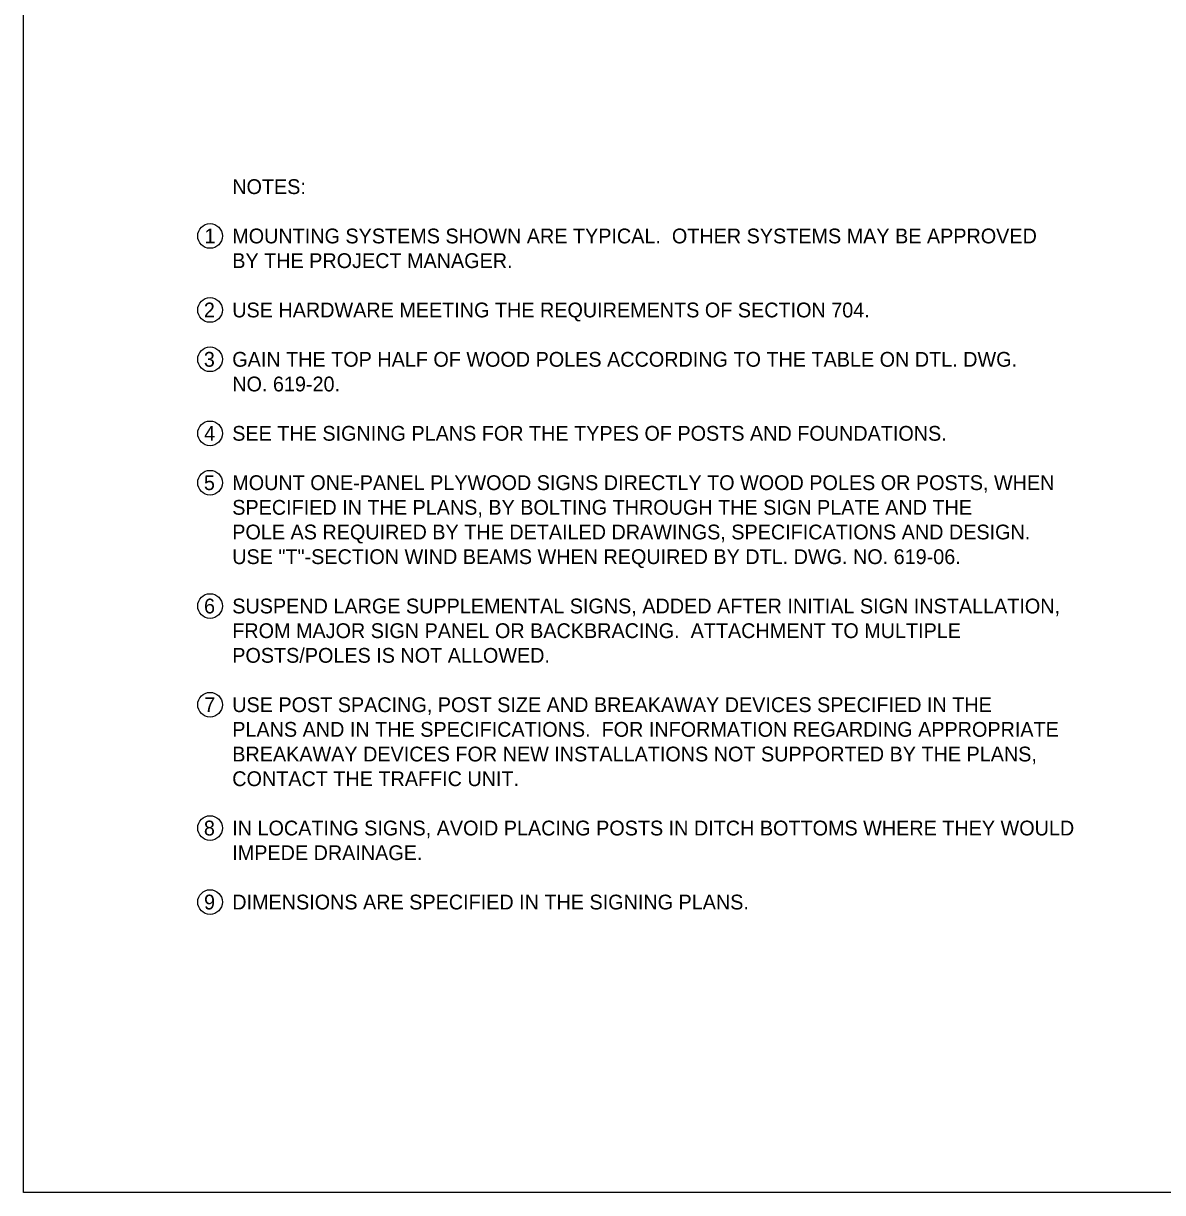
# Model space of a CAD drawing. Extents: x 49991.4 to 50021, y 49987.6 to 50011.4.
# Drawn here: x 49999.384 to 50004.004, y 49987.799 to 49992.538 of the extents above; entities that cross this region are included whole.
import ezdxf

# ---------------------------------------------------------------- set-up
doc = ezdxf.new("R2010")
doc.units = 0
doc.layers.add('Level 1', color=7, linetype='Continuous')
doc.layers.add('Level 2', color=7, linetype='Continuous')

msp = doc.modelspace()

# ---------------------------------------------------------------- linework, layer by layer
at = {"layer": 'Level 1'}
msp.add_lwpolyline([(49999.3835, 49998.9992), (50016.7501, 49998.9992), (50016.7501, 49987.7988), (49999.3835, 49987.7988)], close=True, dxfattribs=at)
at = {"layer": 'Level 2'}
for centre in [(50000.1407, 49991.6766), (50000.1407, 49991.3766), (50000.1407, 49991.1766), (50000.1407, 49990.8766), (50000.1407, 49990.6766), (50000.1407, 49990.1766), (50000.1407, 49989.7766), (50000.1407, 49989.2766), (50000.1407, 49988.9766)]:
    msp.add_circle(centre, 0.05, dxfattribs=at)

# ---------------------------------------------------------------- texts
for s, p in [('NOTES:', (50000.2307, 49991.8466)), ('1', (50000.118, 49991.6466)), ('MOUNTING SYSTEMS SHOWN ARE TYPICAL.  OTHER SYSTEMS MAY BE APPROVED', (50000.2307, 49991.6466)), ('BY THE PROJECT MANAGER.', (50000.2307, 49991.5466)), ('2', (50000.1155, 49991.3466)), ('USE HARDWARE MEETING THE REQUIREMENTS OF SECTION 704.', (50000.2307, 49991.3466)), ('3', (50000.1155, 49991.1466)), ('GAIN THE TOP HALF OF WOOD POLES ACCORDING TO THE TABLE ON DTL. DWG.', (50000.2307, 49991.1466)), ('NO. 619-20.', (50000.2307, 49991.0466)), ('4', (50000.1167, 49990.8466)), ('SEE THE SIGNING PLANS FOR THE TYPES OF POSTS AND FOUNDATIONS.', (50000.2307, 49990.8466)), ('5', (50000.1158, 49990.6466)), ('MOUNT ONE-PANEL PLYWOOD SIGNS DIRECTLY TO WOOD POLES OR POSTS, WHEN', (50000.2307, 49990.6466)), ('SPECIFIED IN THE PLANS, BY BOLTING THROUGH THE SIGN PLATE AND THE', (50000.2307, 49990.5466)), ('POLE AS REQUIRED BY THE DETAILED DRAWINGS, SPECIFICATIONS AND DESIGN.', (50000.2307, 49990.4466)), ('USE "T"-SECTION WIND BEAMS WHEN REQUIRED BY DTL. DWG. NO. 619-06.', (50000.2307, 49990.3466)), ('6', (50000.1162, 49990.1466)), ('SUSPEND LARGE SUPPLEMENTAL SIGNS, ADDED AFTER INITIAL SIGN INSTALLATION,', (50000.2307, 49990.1466)), ('FROM MAJOR SIGN PANEL OR BACKBRACING.  ATTACHMENT TO MULTIPLE', (50000.2307, 49990.0466)), ('POSTS/POLES IS NOT ALLOWED.', (50000.2307, 49989.9466)), ('7', (50000.1169, 49989.7466)), ('USE POST SPACING, POST SIZE AND BREAKAWAY DEVICES SPECIFIED IN THE', (50000.2307, 49989.7466)), ('PLANS AND IN THE SPECIFICATIONS.  FOR INFORMATION REGARDING APPROPRIATE', (50000.2307, 49989.6466)), ('BREAKAWAY DEVICES FOR NEW INSTALLATIONS NOT SUPPORTED BY THE PLANS, ', (50000.2307, 49989.5466)), ('CONTACT THE TRAFFIC UNIT.', (50000.2307, 49989.4466)), ('8', (50000.1157, 49989.2466)), ('IN LOCATING SIGNS, AVOID PLACING POSTS IN DITCH BOTTOMS WHERE THEY WOULD', (50000.2307, 49989.2466)), ('IMPEDE DRAINAGE.', (50000.2307, 49989.1466)), ('9', (50000.1162, 49988.9466)), ('DIMENSIONS ARE SPECIFIED IN THE SIGNING PLANS.', (50000.2307, 49988.9466))]:
    msp.add_text(s, height=0.06, dxfattribs=at).set_placement(p)

doc.saveas('drawing.dxf')
